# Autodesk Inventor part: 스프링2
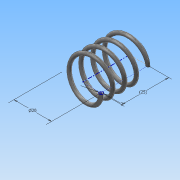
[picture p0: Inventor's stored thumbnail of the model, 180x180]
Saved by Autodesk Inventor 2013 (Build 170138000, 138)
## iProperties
Created: 2016-07
Part Number: 스프링2
Material: 스테인리스강
Document SubType Name: Modeling
Designer: Administrator
Mass: 6.2731 g
Surface Area: 15.7615 cm^2
Volume: 0.776373 cm^3
Density: 8.08 g/cm^3
Author: Administrator
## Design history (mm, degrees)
sketch "스케치1"
  geometry: L1 (0, 0)-(10, 0); L2 (10, 0)-(10, 19.5); L3 (10, 19.5)-(0, 19.5); L4 (0, 19.5)-(0, 0); C1 r 1 at (10, 0)
  constraints: 8 end point, 2 parallel, 1 centre point, 1 coincident, 1 horizontal, 1 perpendicular
  dimensions: "d0" = 20 diameter of L2 L4; "d2" = 2 diameter of C1; "d3" = 19.5 distance of L1.end L2.end (derived)
feature "코일1" pitch "d4" = 10; turns "d6" = 4; dims "d5" = 19.5 (= d3), "d7" = 0, angle "d8" = 90 deg, angle "d9" = 90 deg, "d10" = 0, "d11" = 0
sketch "스케치2"
  geometry: L1 (-11, 0)-(-9, 0) reference; 1 further point
  constraints: 1 horizontal alignment
extrude "돌출1" cut sketch "스케치2" distance "d12" = 10; taper "d13" = 0 deg
node "작업 평면1"
sketch "스케치3"
  geometry: L1 (11, 0)-(9, 0) reference; 1 further point
  constraints: 1 horizontal alignment
extrude "돌출2" cut sketch "스케치3" distance "d14" = 10; taper "d15" = 0 deg
node "솔리드1"
node "절단 모서리 투영1"
node "절단 모서리 투영2"
